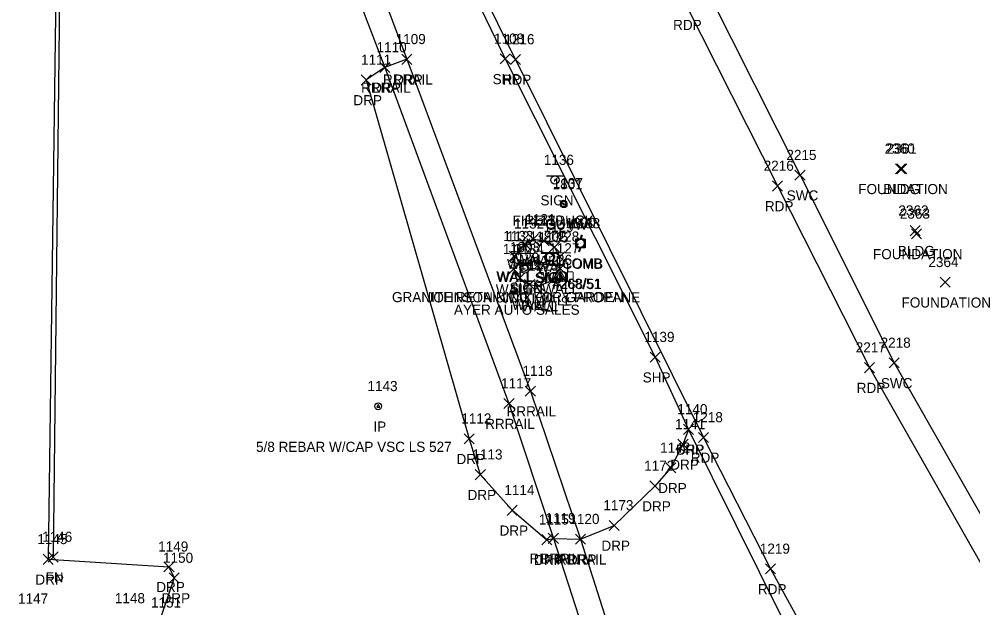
# Model space of a CAD drawing. Extents: x 1635588 to 1637550, y 621583 to 623638.
# Drawn here: x 1636398.5 to 1636586.9, y 622937 to 623053.3 of the extents above; entities that cross this region are included whole.
import ezdxf

# ---------------------------------------------------------------- set-up
doc = ezdxf.new("R2010")
doc.units = 0
for name, color, linetype in [('L_A', 7, 'Continuous'), ('L_C', 7, 'Continuous'), ('L_I', 7, 'Continuous'), ('L_TIC', 7, 'Continuous'), ('LFNC', 7, 'Continuous'), ('LW', 7, 'Continuous'), ('M_A', 7, 'Continuous'), ('M_C', 7, 'Continuous'), ('M_I', 7, 'Continuous'), ('MPIR', 7, 'Continuous'), ('P_A', 7, 'Continuous'), ('P_I', 7, 'Continuous'), ('P_TIC', 7, 'Continuous'), ('PET', 7, 'Continuous'), ('PSP', 7, 'Continuous'), ('R_A', 7, 'Continuous'), ('R_I', 7, 'Continuous'), ('R_TIC', 7, 'Continuous'), ('RDP', 7, 'Continuous'), ('RR', 7, 'Continuous'), ('RSW', 7, 'Continuous'), ('S_A', 7, 'Continuous'), ('S_C', 7, 'Continuous'), ('S_I', 7, 'Continuous'), ('SSGN', 7, 'Continuous'), ('U_A', 7, 'Continuous'), ('U_C', 7, 'Continuous'), ('U_I', 7, 'Continuous'), ('UP', 7, 'Continuous'), ('UPGW', 7, 'Continuous')]:
    doc.layers.add(name, color=color, linetype=linetype)

msp = doc.modelspace()

# ---------------------------------------------------------------- linework, layer by layer
at = {"layer": 'L_TIC'}
for points in [[(1636571.6, 623022.7), (1636573.6, 623024.7)], [(1636573.6, 623022.7), (1636571.6, 623024.7)], [(1636571.88, 623022.71), (1636573.88, 623024.71)], [(1636573.88, 623022.71), (1636571.88, 623024.71)], [(1636574.51, 623010.48), (1636576.51, 623012.48)], [(1636576.51, 623010.48), (1636574.51, 623012.48)], [(1636574.79, 623009.86), (1636576.79, 623011.86)], [(1636576.79, 623009.86), (1636574.79, 623011.86)], [(1636497.39, 623007.91), (1636499.39, 623009.91)], [(1636499.39, 623007.91), (1636497.39, 623009.91)], [(1636499.06, 623008.77), (1636501.06, 623010.77)], [(1636501.06, 623008.77), (1636499.06, 623010.77)], [(1636501.2, 623008.5), (1636503.2, 623010.5)], [(1636503.2, 623008.5), (1636501.2, 623010.5)], [(1636503.24, 623007.25), (1636505.24, 623009.25)], [(1636505.24, 623007.25), (1636503.24, 623009.25)], [(1636495.28, 623005.44), (1636497.28, 623007.44)], [(1636497.28, 623005.44), (1636495.28, 623007.44)], [(1636495.41, 623005.37), (1636497.41, 623007.37)], [(1636497.41, 623005.37), (1636495.41, 623007.37)], [(1636504.32, 623005.33), (1636506.32, 623007.33)], [(1636506.32, 623005.33), (1636504.32, 623007.33)], [(1636495.19, 623002.88), (1636497.19, 623004.88)], [(1636497.19, 623002.88), (1636495.19, 623004.88)], [(1636504.34, 623003.01), (1636506.34, 623005.01)], [(1636506.34, 623003.01), (1636504.34, 623005.01)], [(1636496.43, 623001.13), (1636498.43, 623003.13)], [(1636498.43, 623001.13), (1636496.43, 623003.13)], [(1636498.36, 622999.82), (1636500.36, 623001.82)], [(1636500.36, 622999.82), (1636498.36, 623001.82)], [(1636500.21, 622999.59), (1636502.21, 623001.59)], [(1636502.21, 622999.59), (1636500.21, 623001.59)], [(1636502.96, 623000.72), (1636504.96, 623002.72)], [(1636504.96, 623000.72), (1636502.96, 623002.72)], [(1636580.42, 623000.3), (1636582.42, 623002.3)], [(1636582.42, 623000.3), (1636580.42, 623002.3)], [(1636404.23, 622946.04), (1636406.23, 622948.04)], [(1636406.23, 622946.04), (1636404.23, 622948.04)]]:
    msp.add_lwpolyline(points, dxfattribs=at)
at = {"layer": 'LFNC'}
msp.add_lwpolyline([(1636406.54, 623063.66), (1636405.23, 622947.04)], dxfattribs=at)
at = {"layer": 'LW'}
msp.add_lwpolyline([(1636496.41, 623006.37), (1636496.19, 623003.88), (1636497.43, 623002.13), (1636499.36, 623000.82), (1636501.21, 623000.59), (1636503.96, 623001.72), (1636505.34, 623004.01), (1636505.32, 623006.33), (1636504.24, 623008.25), (1636502.2, 623009.5), (1636500.06, 623009.77), (1636498.39, 623008.91), (1636496.28, 623006.44), (1636496.41, 623006.37)], dxfattribs=at)
at = {"layer": 'MPIR'}
msp.add_lwpolyline([(1636469.44, 622977.14), (1636469.15, 622976.64), (1636469.73, 622976.64)], close=True, dxfattribs=at)
msp.add_circle((1636469.44, 622976.8), 0.667, dxfattribs=at)
at = {"layer": 'P_TIC'}
for points in [[(1636493.51, 623044.42), (1636495.51, 623046.42)], [(1636495.51, 623044.42), (1636493.51, 623046.42)], [(1636495.54, 623044.3), (1636497.54, 623046.3)], [(1636497.54, 623044.3), (1636495.54, 623046.3)], [(1636495.54, 623044.3), (1636497.54, 623046.3)], [(1636497.54, 623044.3), (1636495.54, 623046.3)], [(1636547.33, 623019.32), (1636549.33, 623021.32)], [(1636549.33, 623019.32), (1636547.33, 623021.32)], [(1636523.16, 622985.51), (1636525.16, 622987.51)], [(1636525.16, 622985.51), (1636523.16, 622987.51)], [(1636565.47, 622983.44), (1636567.47, 622985.44)], [(1636567.47, 622983.44), (1636565.47, 622985.44)], [(1636529.74, 622971.24), (1636531.74, 622973.24)], [(1636531.74, 622971.24), (1636529.74, 622973.24)], [(1636532.69, 622969.65), (1636534.69, 622971.65)], [(1636534.69, 622969.65), (1636532.69, 622971.65)], [(1636545.95, 622943.69), (1636547.95, 622945.69)], [(1636547.95, 622943.69), (1636545.95, 622945.69)]]:
    msp.add_lwpolyline(points, dxfattribs=at)
at = {"layer": 'PET'}
for points in [[(1636496.54, 623045.3), (1636474, 623091.38)], [(1636524.76, 623078.53), (1636523.53, 623074.7), (1636523.65, 623069.69), (1636530.21, 623056.13), (1636548.33, 623020.32), (1636566.47, 622984.44), (1636591.76, 622939.94), (1636601.42, 622922.26), (1636608.34, 622909.96), (1636613.87, 622901.12), (1636616.68, 622897.25), (1636624.11, 622894.09), (1636627.52, 622895.36), (1636632.87, 622898.34)], [(1636496.54, 623045.3), (1636533.69, 622970.65), (1636546.95, 622944.69), (1636557.06, 622926.23), (1636579, 622887.89), (1636603.72, 622849.48), (1636616.07, 622830.82), (1636647.79, 622783.76), (1636703.25, 622700.68), (1636737.08, 622649.81), (1636763.83, 622609.67), (1636812.95, 622535.62), (1636858.06, 622468.21), (1636878.24, 622438.26), (1636911.18, 622389.38), (1636974.88, 622293.33), (1636986.61, 622276.7), (1637016.63, 622231.99)]]:
    msp.add_lwpolyline(points, dxfattribs=at)
at = {"layer": 'PSP'}
msp.add_lwpolyline([(1636412.61, 623220.07), (1636436.6, 623167.3), (1636456.23, 623125.07), (1636460.67, 623115.98), (1636475.52, 623084.87), (1636494.51, 623045.42), (1636524.16, 622986.51), (1636530.74, 622972.24), (1636554.07, 622925.3), (1636577.18, 622886.3), (1636601.72, 622847.41), (1636613.46, 622830.09), (1636645.38, 622782.47), (1636700.61, 622698.86), (1636734.28, 622648.07), (1636752.12, 622619.3), (1636752.46, 622616.81), (1636755.34, 622613.42), (1636810.04, 622534.39), (1636855.63, 622465.66), (1636874.76, 622437.49), (1636904.15, 622393.55)], dxfattribs=at)
at = {"layer": 'R_TIC'}
for points in [[(1636474.1, 623044.34), (1636476.1, 623046.34)], [(1636476.1, 623044.34), (1636474.1, 623046.34)], [(1636474.1, 623044.34), (1636476.1, 623046.34)], [(1636476.1, 623044.34), (1636474.1, 623046.34)], [(1636469.76, 623042.73), (1636471.76, 623044.73)], [(1636471.76, 623042.73), (1636469.76, 623044.73)], [(1636469.76, 623042.73), (1636471.76, 623044.73)], [(1636471.76, 623042.73), (1636469.76, 623044.73)], [(1636466.04, 623040.26), (1636468.04, 623042.26)], [(1636468.04, 623040.26), (1636466.04, 623042.26)], [(1636551.77, 623021.45), (1636553.77, 623023.45)], [(1636553.77, 623021.45), (1636551.77, 623023.45)], [(1636570.37, 622984.37), (1636572.37, 622986.37)], [(1636572.37, 622984.37), (1636570.37, 622986.37)], [(1636498.5, 622978.8), (1636500.5, 622980.8)], [(1636500.5, 622978.8), (1636498.5, 622980.8)], [(1636494.27, 622976.34), (1636496.27, 622978.34)], [(1636496.27, 622976.34), (1636494.27, 622978.34)], [(1636529.74, 622971.24), (1636531.74, 622973.24)], [(1636531.74, 622971.24), (1636529.74, 622973.24)], [(1636486.41, 622969.39), (1636488.41, 622971.39)], [(1636488.41, 622969.39), (1636486.41, 622971.39)], [(1636528.64, 622968.28), (1636530.64, 622970.28)], [(1636530.64, 622968.28), (1636528.64, 622970.28)], [(1636488.6, 622962.3), (1636490.6, 622964.3)], [(1636490.6, 622962.3), (1636488.6, 622964.3)], [(1636526.25, 622963.65), (1636528.25, 622965.65)], [(1636528.25, 622963.65), (1636526.25, 622965.65)], [(1636523.11, 622960.06), (1636525.11, 622962.06)], [(1636525.11, 622960.06), (1636523.11, 622962.06)], [(1636494.91, 622955.26), (1636496.91, 622957.26)], [(1636496.91, 622955.26), (1636494.91, 622957.26)], [(1636515.04, 622952.27), (1636517.04, 622954.27)], [(1636517.04, 622952.27), (1636515.04, 622954.27)], [(1636515.04, 622952.27), (1636517.04, 622954.27)], [(1636517.04, 622952.27), (1636515.04, 622954.27)], [(1636501.73, 622949.45), (1636503.73, 622951.45)], [(1636503.73, 622949.45), (1636501.73, 622951.45)], [(1636503.04, 622949.72), (1636505.04, 622951.72)], [(1636505.04, 622949.72), (1636503.04, 622951.72)], [(1636503.04, 622949.72), (1636505.04, 622951.72)], [(1636505.04, 622949.72), (1636503.04, 622951.72)], [(1636508.41, 622949.55), (1636510.41, 622951.55)], [(1636510.41, 622949.55), (1636508.41, 622951.55)], [(1636508.41, 622949.55), (1636510.41, 622951.55)], [(1636510.41, 622949.55), (1636508.41, 622951.55)], [(1636403.22, 622945.58), (1636405.22, 622947.58)], [(1636405.22, 622945.58), (1636403.22, 622947.58)], [(1636427.1, 622944.11), (1636429.1, 622946.11)], [(1636429.1, 622944.11), (1636427.1, 622946.11)], [(1636428.15, 622941.89), (1636430.15, 622943.89)], [(1636430.15, 622941.89), (1636428.15, 622943.89)]]:
    msp.add_lwpolyline(points, dxfattribs=at)
at = {"layer": 'RDP'}
for points in [[(1636426.44, 623136.43), (1636420.98, 623137.1), (1636414.54, 623111.02), (1636407.75, 623097.32), (1636403.36, 623087.01), (1636401.25, 623078.34), (1636401.37, 623068.48), (1636429.73, 623071.8), (1636430.14, 623068.89), (1636406.01, 623065.32), (1636405.81, 623063.86), (1636404.22, 622946.58), (1636428.1, 622945.11), (1636429.15, 622942.89), (1636426.11, 622934.05), (1636419.92, 622924.84), (1636405.51, 622913.03), (1636421.18, 622869.94), (1636453.55, 622783.03), (1636469.62, 622787.52)], [(1636475.1, 623045.34), (1636470.76, 623043.73), (1636467.04, 623041.26), (1636487.41, 622970.39), (1636489.6, 622963.3), (1636495.91, 622956.26), (1636502.73, 622950.45), (1636504.04, 622950.72), (1636509.41, 622950.55), (1636516.04, 622953.27)], [(1636530.74, 622972.24), (1636529.64, 622969.28), (1636527.25, 622964.65), (1636524.11, 622961.06), (1636516.04, 622953.27)]]:
    msp.add_lwpolyline(points, dxfattribs=at)
at = {"layer": 'RR'}
for points in [[(1636406.43, 623208.62), (1636424.65, 623171.19), (1636442.27, 623131.47), (1636462.36, 623079.17), (1636475.1, 623045.34), (1636499.5, 622979.8), (1636509.41, 622950.55), (1636516.07, 622929.71), (1636530.2, 622882.11), (1636568.93, 622740.93), (1636580.62, 622697.82)], [(1636401.96, 623205.78), (1636420.49, 623168.36), (1636437.73, 623129.25), (1636458.96, 623074.5), (1636470.76, 623043.73), (1636495.27, 622977.34), (1636504.04, 622950.72), (1636511.18, 622928.71), (1636525.38, 622880.65), (1636564.25, 622739.19), (1636576, 622696.58)]]:
    msp.add_lwpolyline(points, dxfattribs=at)
at = {"layer": 'RSW'}
msp.add_lwpolyline([(1636524.76, 623078.53), (1636528.35, 623071.35), (1636530.25, 623067.42), (1636534.71, 623058.46), (1636552.77, 623022.45), (1636571.37, 622985.37), (1636595.71, 622942.66), (1636605.64, 622925.15), (1636612.41, 622912.41), (1636617.8, 622903.4), (1636619.7, 622901.31), (1636620.99, 622899.9), (1636623.17, 622899.6), (1636625.06, 622899.88), (1636629.3, 622902.63)], dxfattribs=at)
at = {"layer": 'SSGN'}
for p, q in [((1636502.7, 623022.34), (1636506.04, 623022.34)), ((1636504.35, 623021.5), (1636504.35, 623021.5)), ((1636501.56, 623007.02), (1636504.9, 623007.02)), ((1636501.8, 623007.18), (1636505.14, 623007.18)), ((1636503.21, 623006.19), (1636503.21, 623006.19)), ((1636503.45, 623006.34), (1636503.45, 623006.34)), ((1636496.6, 623005.09), (1636499.93, 623005.09)), ((1636496.69, 623004.74), (1636500.03, 623004.74)), ((1636498.24, 623004.25), (1636498.24, 623004.25)), ((1636498.34, 623003.9), (1636498.34, 623003.9))]:
    msp.add_line(p, q, dxfattribs=at)
for centre in [(1636504.35, 623021.5), (1636503.21, 623006.19), (1636503.45, 623006.34), (1636498.24, 623004.25), (1636498.34, 623003.9)]:
    msp.add_circle(centre, 0.833, dxfattribs=at)
at = {"layer": 'UP'}
for p, q in [((1636508.48, 623008.19), (1636508.48, 623009.86)), ((1636508.48, 623009.86), (1636510.15, 623009.86)), ((1636508.62, 623008.11), (1636508.62, 623009.78)), ((1636508.62, 623009.78), (1636510.29, 623009.78)), ((1636509.56, 623010.69), (1636509.31, 623009.86)), ((1636509.7, 623010.61), (1636509.45, 623009.78)), ((1636510.15, 623009.86), (1636510.15, 623008.19)), ((1636510.29, 623009.78), (1636510.29, 623008.11)), ((1636510.15, 623008.19), (1636508.48, 623008.19)), ((1636510.29, 623008.11), (1636508.62, 623008.11)), ((1636509.06, 623007.36), (1636509.31, 623008.19)), ((1636509.2, 623007.28), (1636509.45, 623008.11)), ((1636509.31, 623009.02), (1636509.31, 623009.02)), ((1636509.45, 623008.95), (1636509.45, 623008.95))]:
    msp.add_line(p, q, dxfattribs=at)
for centre in [(1636509.31, 623009.02), (1636509.45, 623008.95)]:
    msp.add_circle(centre, 0.833, dxfattribs=at)
at = {"layer": 'UPGW'}
for centre, radius in [((1636506.06, 623016.87), 0.625), ((1636506.1, 623016.66), 0.625), ((1636506.06, 623016.87), 0.0833), ((1636506.1, 623016.66), 0.0833)]:
    msp.add_circle(centre, radius, dxfattribs=at)

# ---------------------------------------------------------------- texts
at = {"layer": 'L_A'}
for s, p in [('FOUNDATION', (1636564.27, 623018.71)), ('BLDG', (1636569.19, 623018.7)), ('FOUNDATION', (1636567.18, 623005.86)), ('BLDG', (1636572.1, 623006.48)), ('WALL', (1636494.88, 623003.91)), ('WALL', (1636496.54, 623004.77)), ('WALL', (1636498.69, 623004.5)), ('WALL', (1636492.77, 623001.44)), ('WALL', (1636500.72, 623003.25)), ('WALL', (1636492.9, 623001.37)), ('WALL', (1636501.81, 623001.33)), ('WALL', (1636492.67, 622998.88)), ('WALL', (1636501.83, 622999.01)), ('WALL', (1636493.92, 622997.13)), ('WALL', (1636495.85, 622995.82)), ('WALL', (1636500.45, 622996.72)), ('FOUNDATION', (1636572.82, 622996.3)), ('WALL', (1636497.7, 622995.59)), ('FN', (1636403.71, 622942.04))]:
    msp.add_text(s, height=2, dxfattribs=at).set_placement(p)
at = {"layer": 'L_C'}
msp.add_text('GRANITE RETAINING FOR GARDEN', height=2, dxfattribs=at).set_placement((1636472.16, 622997.37))
at = {"layer": 'L_I'}
for s, p in [('2360', (1636569.48, 623026.71)), ('2361', (1636569.86, 623026.7)), ('1131', (1636498.5, 623012.77)), ('2362', (1636572.2, 623014.48)), ('2363', (1636572.48, 623013.86)), ('1132', (1636496.27, 623011.91)), ('1130', (1636499.99, 623012.5)), ('1129', (1636502.1, 623011.25)), ('1133', (1636494.15, 623009.44)), ('1121', (1636494.85, 623009.37)), ('1128', (1636503.2, 623009.33)), ('1122', (1636494.06, 623006.88)), ('1127', (1636503.22, 623007.01)), ('1123', (1636495.31, 623005.13)), ('1124', (1636497.24, 623003.82)), ('1125', (1636499.08, 623003.59)), ('1126', (1636501.78, 623004.72)), ('2364', (1636578.12, 623004.3)), ('1146', (1636403.05, 622950.04))]:
    msp.add_text(s, height=2, dxfattribs=at).set_placement(p)
at = {"layer": 'M_A'}
msp.add_text('IP', height=2, dxfattribs=at).set_placement((1636468.49, 622971.8))
at = {"layer": 'M_C'}
msp.add_text('5/8 REBAR W/CAP VSC LS 527', height=2, dxfattribs=at).set_placement((1636445.3, 622967.8))
at = {"layer": 'M_I'}
msp.add_text('1143', height=2, dxfattribs=at).set_placement((1636467.31, 622979.8))
at = {"layer": 'P_A'}
for s, p in [('RDP', (1636527.69, 623051.13)), ('SHP', (1636492.05, 623040.42)), ('RDP', (1636494.03, 623040.3)), ('RDP', (1636494.03, 623040.3)), ('RDP', (1636545.82, 623015.32)), ('SHP', (1636521.69, 622981.51)), ('RDP', (1636563.96, 622979.44)), ('SHP', (1636528.27, 622967.24)), ('RDP', (1636531.18, 622965.65)), ('RDP', (1636544.44, 622939.69))]:
    msp.add_text(s, height=2, dxfattribs=at).set_placement(p)
at = {"layer": 'P_I'}
for s, p in [('1108', (1636492.31, 623048.42)), ('1216', (1636494.36, 623048.3)), ('1216', (1636494.36, 623048.3)), ('2216', (1636545.58, 623023.32)), ('1139', (1636522.02, 622989.51)), ('2217', (1636563.78, 622987.44)), ('1140', (1636528.53, 622975.24)), ('1218', (1636531.57, 622973.65)), ('1219', (1636544.82, 622947.69))]:
    msp.add_text(s, height=2, dxfattribs=at).set_placement(p)
at = {"layer": 'R_A'}
for s, p in [('RRRAIL', (1636470.39, 623040.34)), ('DRP', (1636472.58, 623040.34)), ('RRRAIL', (1636466.05, 623038.73)), ('DRP', (1636468.25, 623038.73)), ('DRP', (1636464.53, 623036.26)), ('SWC', (1636550.13, 623017.45)), ('SWC', (1636568.74, 622980.37)), ('RRRAIL', (1636494.79, 622974.8)), ('RRRAIL', (1636490.56, 622972.34)), ('DRP', (1636528.23, 622967.24)), ('DRP', (1636484.9, 622965.39)), ('DRP', (1636527.13, 622964.28)), ('DRP', (1636487.09, 622958.3)), ('DRP', (1636524.74, 622959.65)), ('DRP', (1636521.59, 622956.06)), ('DRP', (1636493.4, 622951.26)), ('DRP', (1636513.53, 622948.27)), ('DRP', (1636513.53, 622948.27)), ('RRRAIL', (1636499.33, 622945.72)), ('DRP', (1636500.22, 622945.45)), ('DRP', (1636501.53, 622945.72)), ('RRRAIL', (1636504.7, 622945.55)), ('DRP', (1636506.9, 622945.55)), ('DRP', (1636401.71, 622941.58)), ('DRP', (1636425.59, 622940.11)), ('DRP', (1636426.63, 622937.89))]:
    msp.add_text(s, height=2, dxfattribs=at).set_placement(p)
at = {"layer": 'R_I'}
for s, p in [('1110', (1636469.11, 623046.73)), ('1110', (1636469.11, 623046.73)), ('1109', (1636472.88, 623048.34)), ('1109', (1636472.88, 623048.34)), ('1111', (1636466.05, 623044.26)), ('2215', (1636550.07, 623025.45)), ('2218', (1636568.68, 622988.37)), ('1118', (1636497.94, 622982.8)), ('1117', (1636493.71, 622980.34)), ('1140', (1636528.53, 622975.24)), ('1112', (1636485.85, 622973.39)), ('1141', (1636528.08, 622972.28)), ('1142', (1636525.13, 622967.65)), ('1113', (1636488.04, 622966.3)), ('1172', (1636521.98, 622964.06)), ('1114', (1636494.36, 622959.26)), ('1173', (1636513.91, 622956.27)), ('1173', (1636513.91, 622956.27)), ('1115', (1636501.17, 622953.45)), ('1119', (1636502.47, 622953.72)), ('1119', (1636502.47, 622953.72)), ('1120', (1636507.2, 622953.55)), ('1120', (1636507.2, 622953.55)), ('1145', (1636402.1, 622949.58)), ('1149', (1636425.97, 622948.11)), ('1150', (1636426.93, 622945.89)), ('1151', (1636424.55, 622937.05))]:
    msp.add_text(s, height=2, dxfattribs=at).set_placement(p)
at = {"layer": 'S_A'}
for p in [(1636501.49, 623016.48), (1636500.35, 623001.17), (1636500.59, 623001.32), (1636495.38, 622999.23), (1636495.48, 622998.88)]:
    msp.add_text('SIGN', height=2, dxfattribs=at).set_placement(p)
at = {"layer": 'S_C'}
for s, p in [('FIRE TRUCK', (1636495.97, 623012.48)), ('JOHNSON & DIX OIL & PROPANE', (1636478.99, 622997.32)), ('AYER AUTO SALES', (1636484.4, 622994.88))]:
    msp.add_text(s, height=2, dxfattribs=at).set_placement(p)
at = {"layer": 'S_I'}
for s, p in [('1136', (1636502.15, 623024.48)), ('1802', (1636500.66, 623009.32)), ('1135', (1636501.07, 623009.17)), ('1803', (1636495.45, 623007.23)), ('1134', (1636496.19, 623006.88))]:
    msp.add_text(s, height=2, dxfattribs=at).set_placement(p)
at = {"layer": 'U_A'}
for s, p in [('GUYW', (1636502.45, 623011.87)), ('GUYW', (1636502.49, 623011.66)), ('COMB', (1636505.7, 623004.02)), ('COMB', (1636505.84, 623003.95))]:
    msp.add_text(s, height=2, dxfattribs=at).set_placement(p)
at = {"layer": 'U_C'}
for p in [(1636503.8, 623000.02), (1636503.94, 622999.95)]:
    msp.add_text('#268/51', height=2, dxfattribs=at).set_placement(p)
at = {"layer": 'U_I'}
for s, p in [('1801', (1636503.89, 623019.66)), ('1137', (1636503.93, 623019.87)), ('1800', (1636506.45, 623012.02)), ('1138', (1636507.33, 623011.95)), ('1147', (1636398.29, 622937.83)), ('1148', (1636417.41, 622937.9))]:
    msp.add_text(s, height=2, dxfattribs=at).set_placement(p)

doc.saveas('drawing.dxf')
